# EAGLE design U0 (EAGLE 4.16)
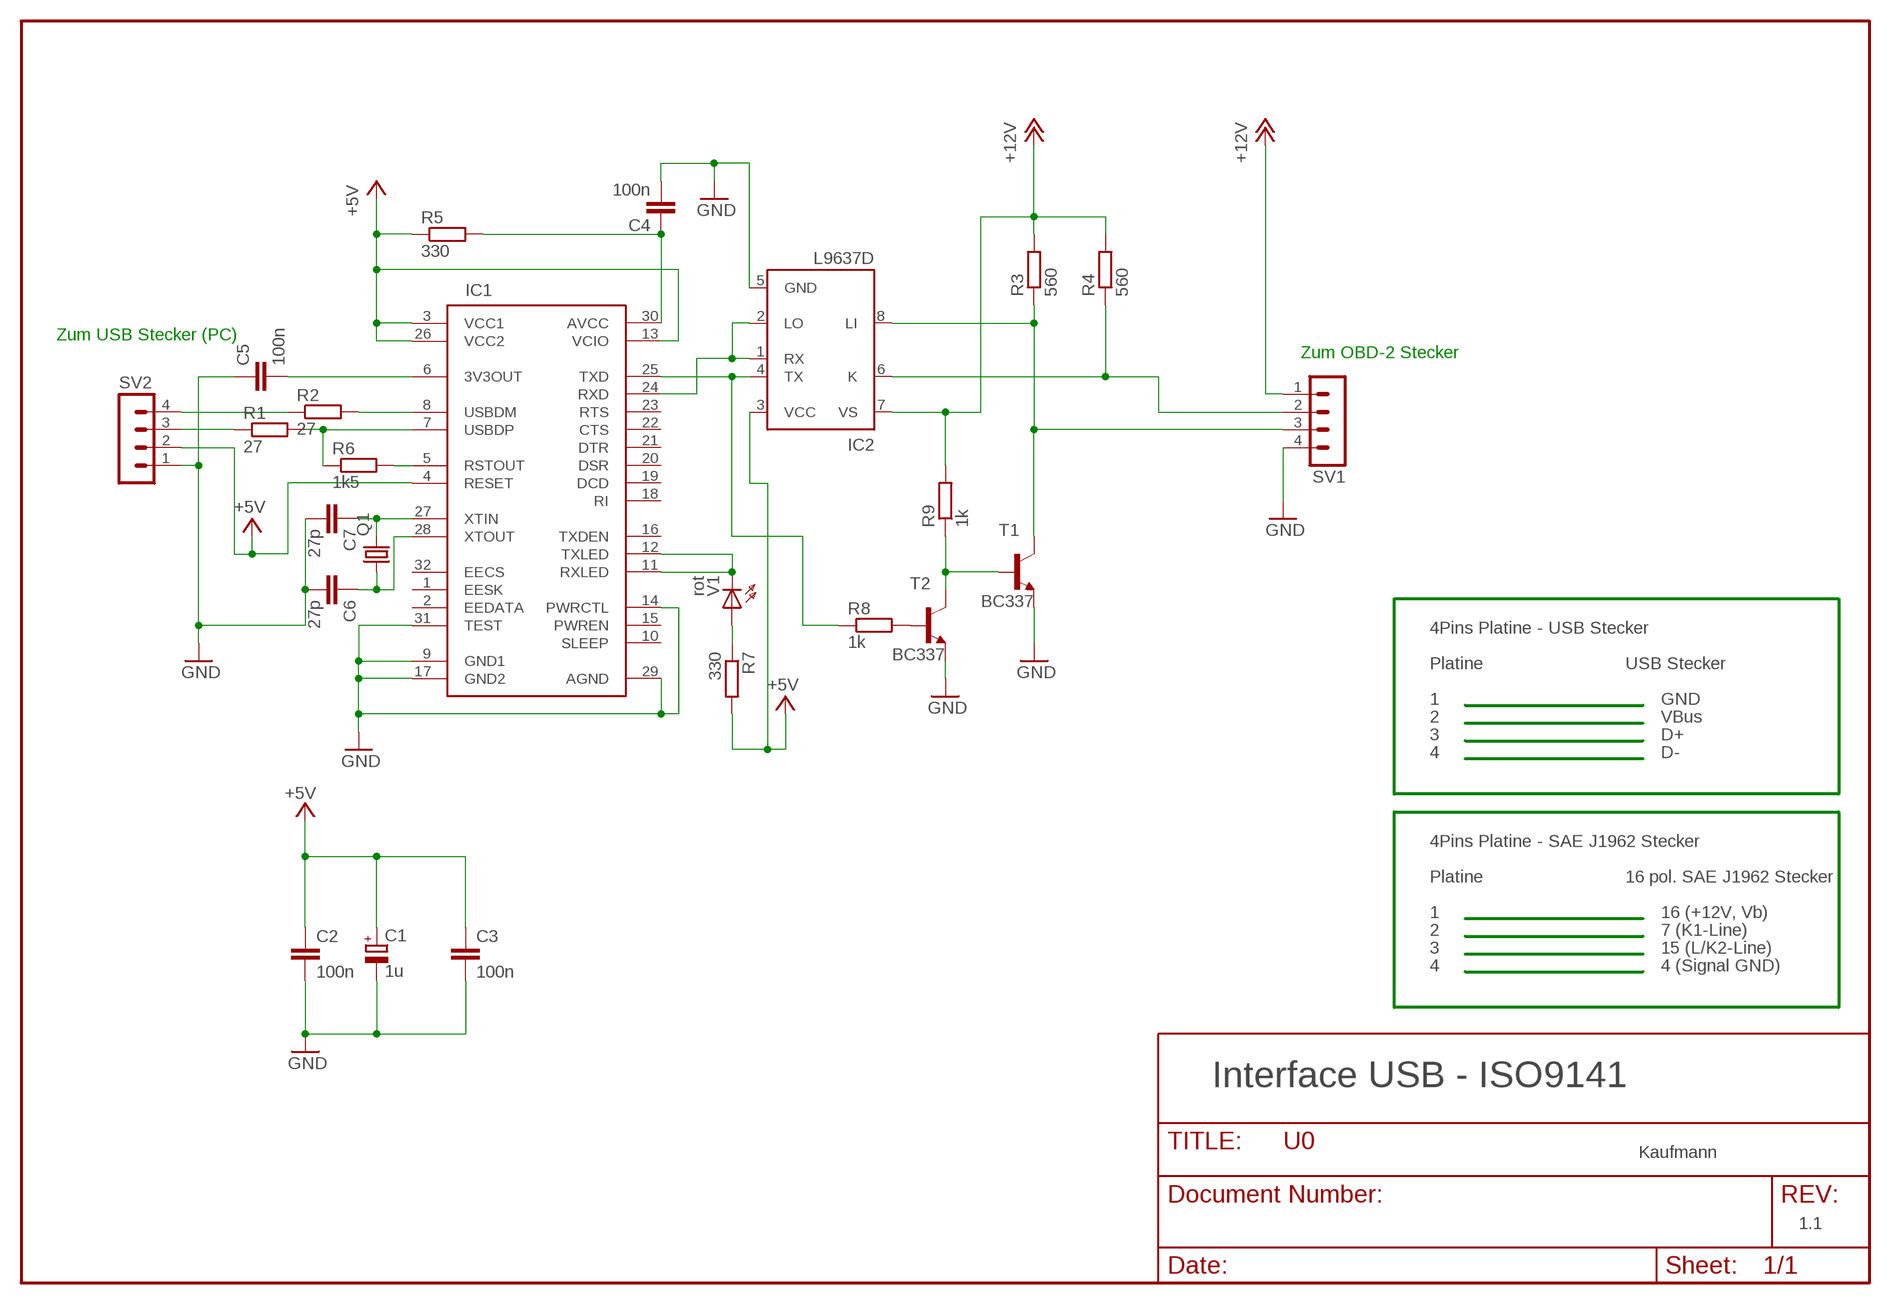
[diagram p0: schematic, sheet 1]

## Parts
C1  1u  CPOL-EUE2-5  [E2-5]
C2  100n  C-EU025-025X050  [C025-025X050]
C3  100n  C-EU025-025X050  [C025-025X050]
C4  100n  C-EU025-025X050  [C025-025X050]
C5  100n  C-EU025-025X050  [C025-025X050]
C6  27p  C-EU025-025X050  [C025-025X050]
C7  27p  C-EU025-025X050  [C025-025X050]
IC1  FT232BM  [QFP-32]
IC2  L9637D  [SO08]
Q1  CRYSTALHC18U-V  [HC18U-V]
R1  27  R-EU_0207/10  [0207/10]
R2  27  R-EU_0207/10  [0207/10]
R3  560  R-EU_0207/10  [0207/10]
R4  560  R-EU_0207/10  [0207/10]
R5  330  R-EU_0207/10  [0207/10]
R6  1k5  R-EU_0207/10  [0207/10]
R7  330  R-EU_0207/10  [0207/10]
R8  1k  R-EU_0207/10  [0207/10]
R9  1k  R-EU_0207/10  [0207/10]
SV1  MA04-1  [MA04-1]
SV2  MA04-1  [MA04-1]
T1  BC337  BC337-40  [TO92]
T2  BC337  BC337-40  [TO92]
V1  rot  LED3MM  [LED3MM]

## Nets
+5V [Power]: C1.+ C2.1 C3.1 IC1.3(VCC1) IC1.4(RESET) IC1.13(VCIO) IC1.26(VCC2) IC2.3(VCC) R5.1 R7.2 SV2.2
+12V: IC2.7(VS) R3.2 R4.2 R9.2 SV1.1
GND [Power]: C1.- C2.2 C3.2 C4.2 C5.1 C6.2 C7.2 IC1.9(GND1) IC1.14(PWRCTL) IC1.17(GND2) IC1.29(AGND) IC1.31(TEST) IC2.5(GND) SV1.4 SV2.1 T1.1(E) T2.1(E)
N$1: R2.1 SV2.4
N$2: IC1.8(USBDM) R2.2
N$4: R1.1 SV2.3
N$5: IC1.7(USBDP) R1.2 R6.1
N$6: IC1.5(RSTOUT) R6.2
N$7: IC2.8(LI) R3.1 SV1.3 T1.3(C)
N$8: IC1.11(RXLED) IC1.12(TXLED) V1.K(C)
N$9: C5.2 IC1.6(3V3OUT)
N$10: C4.1 IC1.30(AVCC) R5.2
N$11: C7.1 IC1.27(XTIN) Q1.2
N$12: IC2.6(K) R4.1 SV1.2
N$13: C6.1 IC1.28(XTOUT) Q1.1
N$14: R8.2 T2.2(B)
N$16: IC1.25(TXD) IC2.4(TX) R8.1
N$17: R7.1 V1.A
N$18: R9.1 T1.2(B) T2.3(C)
N$20: IC1.24(RXD) IC2.1(RX) IC2.2(LO)
Unconnected: IC1.1(EESK) IC1.2(EEDATA) IC1.10(SLEEP) IC1.15(PWREN) IC1.16(TXDEN) IC1.18(RI) IC1.19(DCD) IC1.20(DSR) IC1.21(DTR) IC1.22(CTS) IC1.23(RTS) IC1.32(EECS)

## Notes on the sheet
- Zum USB Stecker (PC)
- Zum OBD-2 Stecker
- 4Pins Platine - USB Stecker
- Platine | USB Stecker
- 1 | GND
- 2 | VBus
- 3 | D+
- 4 | D-
- 4Pins Platine - SAE J1962 Stecker
- Platine | 16 pol. SAE J1962 Stecker
- 1 | 16 (+12V, Vb)
- 2 | 7 (K1-Line)
- 3 | 15 (L/K2-Line)
- 4 | 4 (Signal GND)
- Interface USB - ISO9141
- Kaufmann
- 1.1

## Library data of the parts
C1 = rcl:CPOL-EU: POLARIZED CAPACITOR, European symbol
C2-C7 = rcl:C-EU: CAPACITOR, European symbol
IC1 = FTDI:FT232BM: FT232BM USB-RS232 Wandler FTDI
IC2 = st-microelectronics:L9637D: ISO 9141 INTERFACE Source: 1765.pdf
Q1 = crystal:CRYSTAL: CRYSTAL
R1-R9 = rcl:R-EU_: RESISTOR, European symbol
SV1 SV2 = con-lstb:MA04-1: PIN HEADER
T1 T2 = transistor-npn:BC337*: NPN Transistor
V1 = led:LED: LED

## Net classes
0 default: width 0.305 mm, drill 0.305 mm
1 Power: width 0.406 mm, drill 0.305 mm

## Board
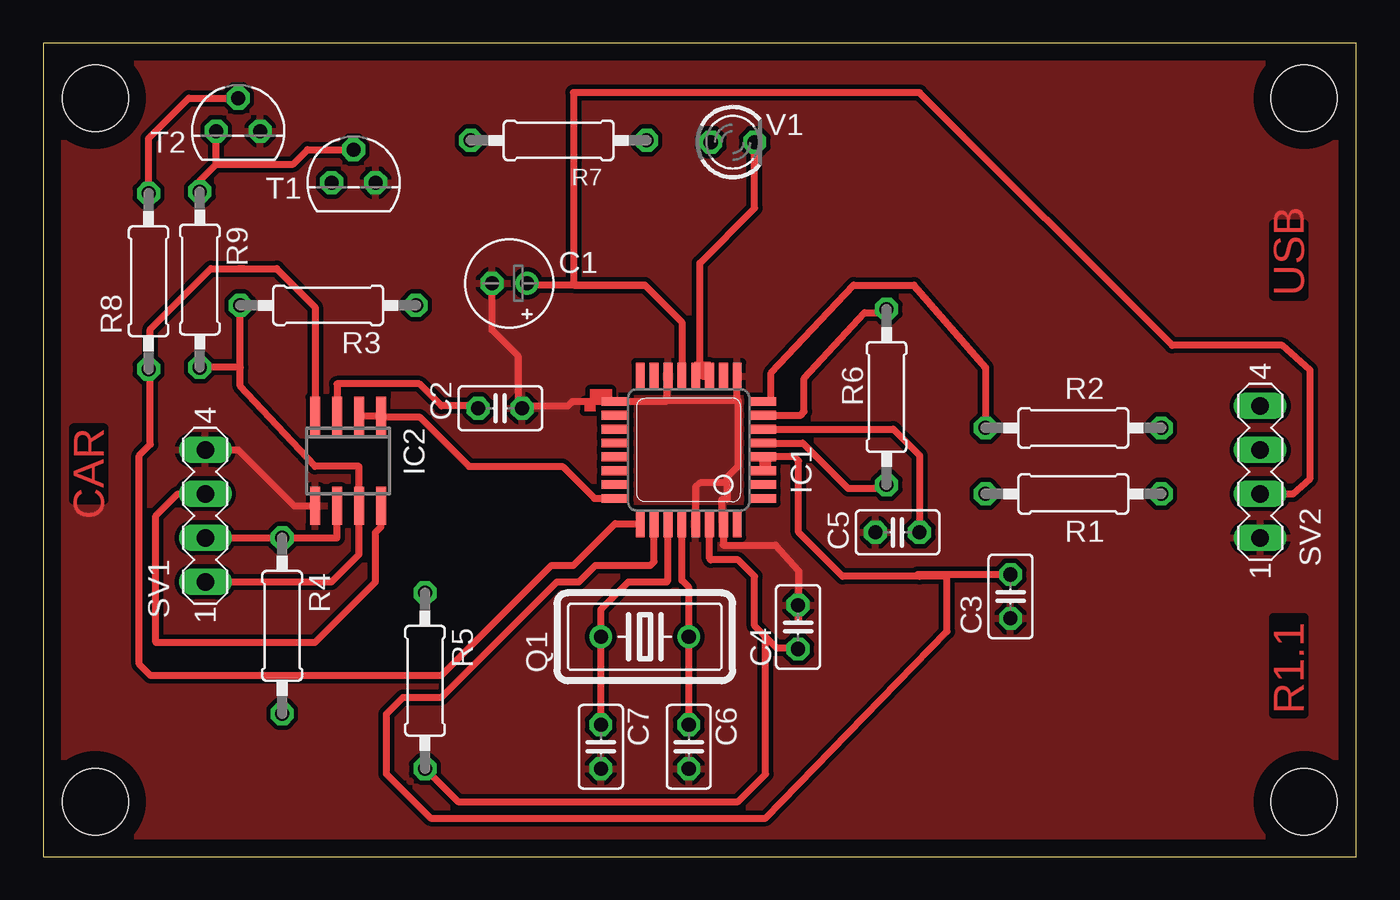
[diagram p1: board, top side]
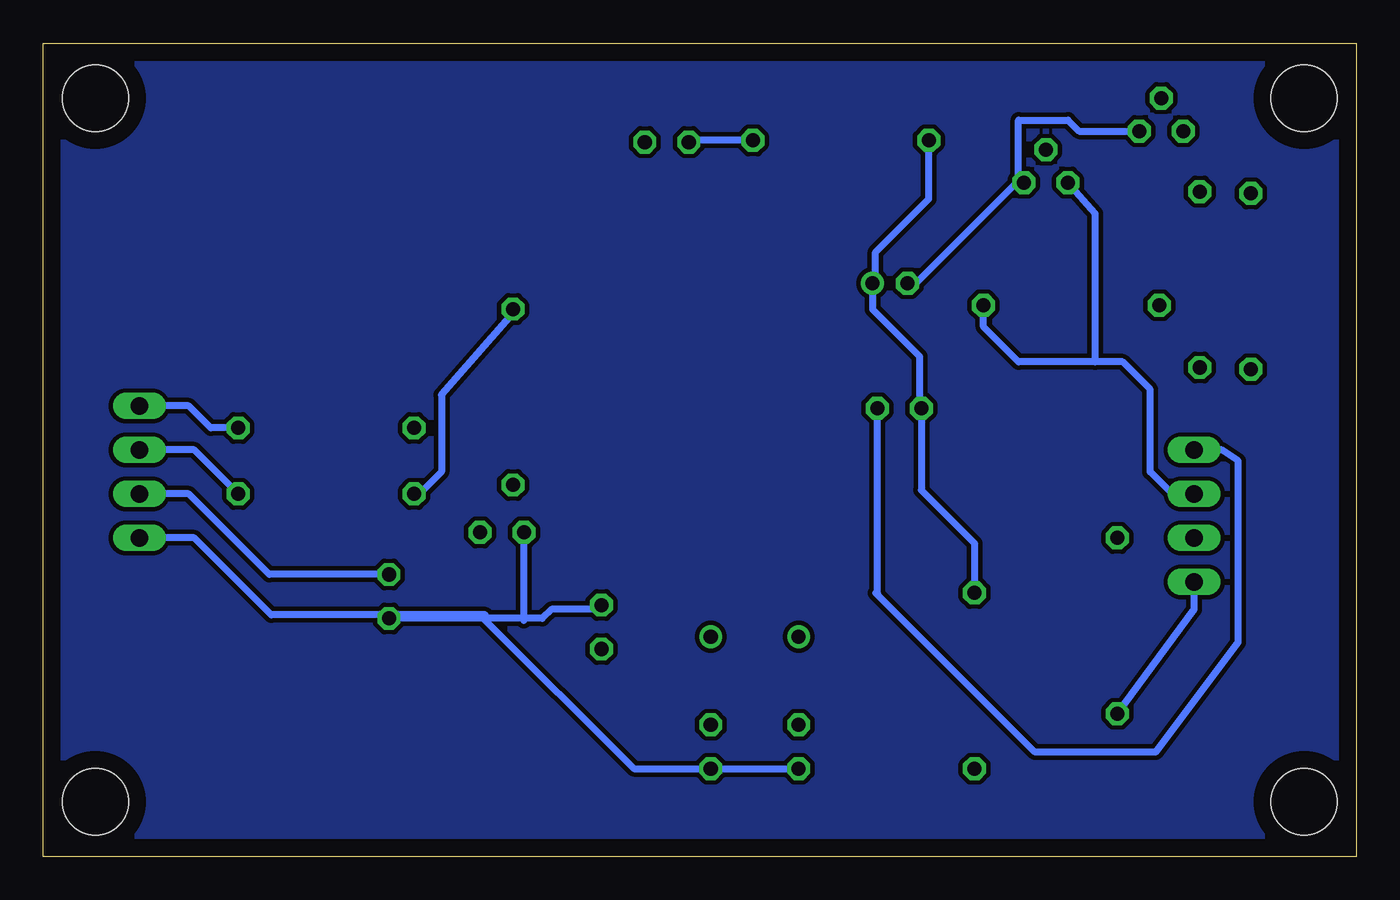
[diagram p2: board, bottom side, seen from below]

Size 75.87 x 46.98 mm. Coordinates in mm from the lower left corner, seen from the top.
Outline: 0,0 75.87,0 75.87,46.98 0,46.98 0,0
Copper layers (1*16): Top 0.035mm / dielectric 1.5mm / Bottom 0.035mm
Design rules "default": minimum track width 10mil, minimum drill 24mil, track to track 10mil, track to pad 10mil, pad to pad 10mil, via to via 10mil, smd to smd 10mil, copper to edge 40mil, drill to drill 8mil, minimum pad ring 10mil, minimum via ring 10mil, stop-mask expansion 4mil, vias tented up to drill 0mil, thermal gap 10mil
Holes 3.81 mm at 3.01,3.17 72.86,3.17 3.01,43.81 72.86,43.81

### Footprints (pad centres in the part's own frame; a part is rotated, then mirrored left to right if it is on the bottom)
E2-5 = drill 0.813 pad 1.27 round: + -1.016,0 | drill 0.813 pad 1.27 octagon: - 1.016,0
C025-025X050 = drill 0.813 octagon: 1 -1.27,0; 2 1.27,0
QFP-32 = smd 0.508 x 1.6: 1 -2.8,-4.25; 2 -2,-4.25; 3 -1.2,-4.25; 4 -0.4,-4.25; 5 0.4,-4.25; 6 1.2,-4.25; 7 2,-4.25; 8 2.8,-4.25; 17 2.8,4.25; 18 2,4.25; 19 1.2,4.25; 20 0.4,4.25; 21 -0.4,4.25; 22 -1.2,4.25; 23 -2,4.25; 24 -2.8,4.25 | smd 1.6 x 0.508: 9 4.25,-2.8; 10 4.25,-2; 11 4.25,-1.2; 12 4.25,-0.4; 13 4.25,0.4; 14 4.25,1.2; 15 4.25,2; 16 4.25,2.8; 25 -4.25,2.8; 26 -4.25,2; 27 -4.25,1.2; 28 -4.25,0.4; 29 -4.25,-0.4; 30 -4.25,-1.2; 31 -4.25,-2; 32 -4.25,-2.8
SO08 = smd 0.6 x 2.2: 1 -1.905,-2.6; 2 -0.635,-2.6; 3 0.635,-2.6; 4 1.905,-2.6; 5 1.905,2.6; 6 0.635,2.6; 7 -0.635,2.6; 8 -1.905,2.6
HC18U-V = drill 0.813 round: 1 -2.54,0; 2 2.54,0
0207/10 = drill 0.813 octagon: 1 -5.08,0; 2 5.08,0
MA04-1 = drill 1.016 long: 1 -3.81,0; 2 -1.27,0; 3 1.27,0; 4 3.81,0
TO92 = drill 0.813 octagon: 1 1.27,0; 2 0,1.905; 3 -1.27,0
LED3MM = drill 0.813 octagon: A -1.27,0; K 1.27,0

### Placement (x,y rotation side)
C1  26.94,33.12 180 top
C2  26.4,25.89 0 top
C3  55.9,15.03 270 top
C4  43.62,13.26 90 top
C5  49.37,18.73 0 top
C6  37.3,6.34 270 top
C7  32.22,6.34 270 top
IC1  37.3,23.49 90 top
IC2  17.61,22.86 180 top
Q1  34.76,12.7 180 top
R1  59.52,20.95 180 top
R2  59.52,24.76 180 top
R3  16.46,31.84 180 top
R4  13.81,13.33 270 top
R5  22.06,10.16 270 top
R6  48.73,26.55 270 top
R7  29.78,41.37 180 top
R8  6.08,33.23 90 top
R9  9.04,33.33 270 top
SV1  9.36,19.68 90 top
SV2  70.32,22.22 90 top
T1  17.93,38.93 0 top
T2  11.27,41.91 0 top
V1  39.84,41.27 0 top

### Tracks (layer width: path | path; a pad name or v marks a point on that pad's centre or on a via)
+5V
  Top 0.406: 41.51,23.09 IC1.4 | IC1.3 41.55,23.05 41.51,23.09 | IC2.3 16.98,27.3 21.74,27.3 23.01,26.03 25.23,26.03 25.13,25.93 C2.1 | C1.+ 27.99,33.12 28.09,33.02 34.76,33.02 | IC1.26 35.3,17.04 35.08,16.82 31.9,16.82 30.95,15.87 29.68,15.87 23.01,9.2 20.79,9.2 19.84,8.25 19.84,4.76 22.38,2.22 41.74,2.22 52.22,13.01 52.22,16.19 50.63,16.19 | 50.63,16.19 50.53,16.29 C3.1 | IC1.13 36.9,30.88 34.76,33.02 | 34.76,33.02 30.63,33.02 30.63,44.13 50.63,44.13 65.24,29.52 71.59,29.52 73.21,28.1 73.21,21.84 72.22,20.95 SV2.2 | 41.51,23.09 43.41,23.09 43.65,22.86 43.65,18.73 46.19,16.19 50.63,16.19
  Bottom 0.406: R7.2 24.7,38 27.77,34.92 27.77,33.65 28.31,33.12 | 28.31,33.12 28.41,33.02 | 28.31,33.12 C1.+ 27.96,31.61 25.23,28.89 25.23,26.03 25.13,25.93 C2.1 25.13,21.17 22.06,18.09 R5.1 | C3.1 62.81,16.29 67.46,20.95 SV2.2
+12V
  Top 0.406: SV1.1 16.66,15.87 18.25,17.46 IC2.7 18.25,22.54 15.71,22.54 11.38,27.18 11.38,28.25 | 11.38,28.25 R3.2 | 11.38,28.25 R9.2
  Bottom 0.406: R4.2 9.36,14.28 SV1.1
GND
  Top 0.406: 36.03,26.35 35.97,26.29 IC1.17 30.57,26.29 30.31,26.03 27.77,26.03 | IC1.14 36.1,27.69 36.03,27.62 36.03,26.35 | IC1.9 40.1,26.4 40.16,26.35 | 36.03,26.35 40.16,26.35 | 40.16,26.35 40.16,22.54 39.52,21.9 39.52,21.58 | 39.52,21.58 39.52,20.63 39.2,20.63 39.2,19.36 39.3,19.27 IC1.31 39.3,18 42.31,17.99 43.65,16.5 43.65,13.65 43.62,14.88 C4.2 | IC1.29 37.7,21.35 37.94,21.58 39.52,21.58 | SV1.4 11.27,23.49 14.5,20.25 IC2.5 | C1.- 25.92,30.42 27.46,28.89 27.46,26.35 27.77,26.03 | 27.77,26.03 27.67,25.93 C2.2
  Bottom 0.406: C7.2 C6.2 41.74,5.08 50.5,13.83 | 50.5,13.83 50.63,13.97 | C3.2 50.5,13.83 | 48.09,13.76 47.03,13.76 46.51,14.28 43.97,14.28 43.65,14.6 43.62,14.57 C4.2 | 48.09,13.76 C3.2 | SV2.1 67.14,18.41 62.7,13.97 50.32,13.97 50.5,13.78 C3.2 | C1.- 25.65,33.12 25.55,33.02 19.64,38.93 T1.1 19.52,38.93 19.52,42.54 16.66,42.54 16.03,41.91 T2.1 | 27.67,15.24 C2.2 | 27.67,15.24 27.67,15.14 | SV1.4 7.77,23.49 6.82,22.86 6.82,12.38 11.58,6.03 18.57,6.03 27.77,15.24 27.67,15.24 | 48.09,13.76 48.09,13.65 | 48.09,13.76 C5.1
  pour Top: 0.47,46.35 75.4,46.35 75.4,0.63 0.47,0.63
N$1
  Bottom 0.406: R2.1 66.19,24.76 67.46,26.03 SV2.4
N$2
  Top 0.406: R2.2 54.45,28.25 50.32,33.02 46.82,33.02 42.06,27.93 42.06,26.35 41.43,26.35 41.48,26.29 IC1.8
N$3
  pour Bottom: 0.47,46.35 75.4,46.35 75.4,0.63 0.47,0.63
N$4
  Bottom 0.406: R1.1 67.14,23.49 SV2.3
N$5
  Top 0.406: IC1.7 43.74,25.49 43.97,25.71 43.97,27.62 47.46,31.43 48.73,31.43 R6.1
  Bottom 0.406: R6.1 48.53,31.63 52.86,26.66 52.86,22.22 54.45,20.63 R1.2
N$6
  Top 0.406: IC1.5 43.88,23.89 46.51,21.27 48.73,21.27 R6.2
N$7
  Top 0.406: SV1.3 7.77,20.95 6.5,19.68 6.5,12.38 15.71,12.38 19.2,15.87 19.2,18.73 19.52,19.04 IC2.8
  Bottom 0.406: R3.1 21.54,30.59 19.52,28.57 15.08,28.57 | SV1.3 10.63,20.95 11.9,22.22 11.9,26.98 13.49,28.57 15.08,28.57 | 15.08,28.57 15.08,37.14 T1.3
N$8
  Top 0.406: 37.94,27.93 37.74,27.74 IC1.12 | IC1.11 38.13,27.74 37.94,27.93 | 37.94,27.93 37.94,34.29 41.11,37.46 V1.K
N$9
  Top 0.406: IC1.6 49.12,24.69 50.63,23.17 C5.2
N$10
  Top 0.406: IC1.30 38.5,17.21 38.57,17.14 40.16,17.14 41.11,16.19 41.11,13.33 41.74,12.7 | 41.74,12.7 42.38,12.06 43.65,12.06 43.62,12.03 C4.1 | R5.2 23.96,3.17 40.16,3.17 41.74,4.76 41.74,12.7
N$11
  Top 0.406: IC1.27 36.1,15.94 36.03,15.87 33.81,15.87 32.22,14.28 Q1.2 C7.1 32.22,7.3
N$12
  Top 0.406: SV1.2 11.9,18.41 R4.1 16.98,18.41 IC2.6
N$13
  Top 0.406: IC1.28 36.9,15.95 37.3,15.55 Q1.1 C6.1
N$14
  Top 0.406: R8.2 6.08,41.49 8.41,43.81 T2.2
N$16
  Top 0.406: IC1.25 33.05,19.24 30.63,16.82 29.36,16.82 23.01,10.47 6.18,10.47 5.55,11.11 5.55,23.17 6.18,23.81 6.18,28.25 | IC2.4 15.71,31.74 13.49,33.97 11.58,33.97 | 11.58,33.97 11.27,33.97 | 6.18,28.25 6.18,28.15 | 6.18,28.15 R8.1 6.18,28.25 | 6.18,28.15 6.18,27.93 | 6.18,28.25 6.18,30.47 9.68,33.97 11.58,33.97
N$17
  Bottom 0.406: R7.1 38.47,41.37 V1.A
N$18
  Top 0.406: T1.2 15.28,40.84 14.44,40 10,40 | 10,40 9.04,39.05 R9.1 | 10,40 T2.3
N$20
  Top 0.406: IC1.24 31.84,20.69 30,22.54 24.6,22.54 21.74,25.39 19.52,25.39 IC2.1 18.31,25.45 18.25,25.39 IC2.2
(copper drawn outside any net)
  shapes: Top area x6

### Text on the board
Top: USB | CAR | R1.1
